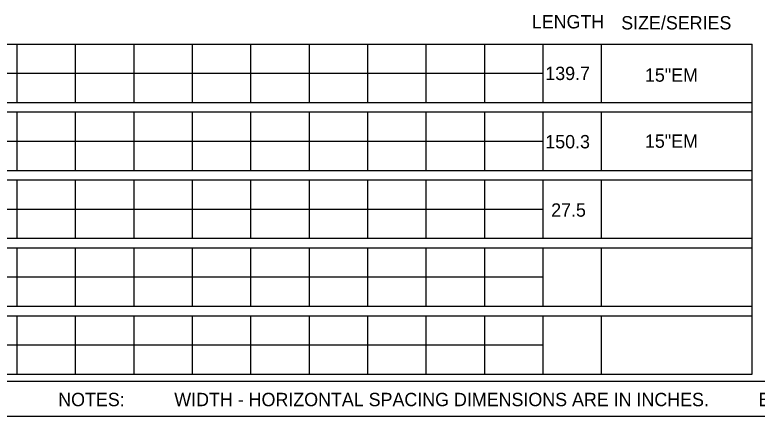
# Model space of a CAD drawing. Extents: x 10268147 to 10268469, y 2141099 to 2141204.
# Drawn here: x 10268190.55 to 10268229.47, y 2141108.6 to 2141129.63 of the extents above; entities that cross this region are included whole.
import ezdxf

# ---------------------------------------------------------------- set-up
doc = ezdxf.new("R2010")
doc.units = 0
for name, color, linetype in [('61', 7, 'Continuous'), ('GSDims', 7, 'Continuous'), ('North Arrow', 7, 'Continuous'), ('SheetLinesMisc2_dp', 7, 'Continuous'), ('TextMisc', 7, 'Continuous'), ('TextNotes', 7, 'Continuous')]:
    doc.layers.add(name, color=color, linetype=linetype)

msp = doc.modelspace()

# ---------------------------------------------------------------- linework, layer by layer
at = {"layer": '61'}
for p, q in [((10268153.875, 2141128.105), (10268229.209, 2141128.105)), ((10268190.65, 2141128.105), (10268190.65, 2141125.045)), ((10268193.714, 2141128.105), (10268193.714, 2141125.045)), ((10268196.779, 2141128.105), (10268196.779, 2141125.045)), ((10268199.843, 2141128.105), (10268199.843, 2141125.045)), ((10268202.908, 2141128.105), (10268202.908, 2141125.045)), ((10268205.972, 2141128.105), (10268205.972, 2141125.045)), ((10268209.037, 2141128.105), (10268209.037, 2141125.045)), ((10268212.102, 2141128.105), (10268212.102, 2141125.045)), ((10268215.166, 2141128.105), (10268215.166, 2141125.045)), ((10268218.232, 2141128.105), (10268218.232, 2141125.045)), ((10268221.296, 2141128.105), (10268221.296, 2141125.045)), ((10268229.209, 2141110.806), (10268229.209, 2141128.105)), ((10268153.875, 2141126.574), (10268218.232, 2141126.575)), ((10268153.875, 2141125.045), (10268229.209, 2141125.045)), ((10268153.875, 2141124.546), (10268229.209, 2141124.546)), ((10268190.65, 2141124.546), (10268190.65, 2141121.485)), ((10268193.714, 2141124.546), (10268193.714, 2141121.485)), ((10268196.779, 2141124.546), (10268196.779, 2141121.485)), ((10268199.843, 2141124.546), (10268199.843, 2141121.485)), ((10268202.908, 2141124.546), (10268202.908, 2141121.485)), ((10268205.972, 2141124.546), (10268205.972, 2141121.485)), ((10268209.037, 2141124.546), (10268209.037, 2141121.485)), ((10268212.102, 2141124.546), (10268212.102, 2141121.485)), ((10268215.166, 2141124.546), (10268215.166, 2141121.485)), ((10268218.232, 2141124.546), (10268218.232, 2141121.485)), ((10268221.296, 2141124.546), (10268221.296, 2141121.485)), ((10268153.875, 2141123.015), (10268218.232, 2141123.015)), ((10268153.875, 2141121.485), (10268229.209, 2141121.485)), ((10268153.875, 2141120.986), (10268229.209, 2141120.986)), ((10268190.65, 2141120.986), (10268190.65, 2141117.925)), ((10268193.714, 2141120.986), (10268193.714, 2141117.925)), ((10268196.779, 2141120.986), (10268196.779, 2141117.925)), ((10268199.843, 2141120.986), (10268199.843, 2141117.925)), ((10268202.908, 2141120.986), (10268202.908, 2141117.925)), ((10268205.972, 2141120.986), (10268205.972, 2141117.925)), ((10268209.037, 2141120.986), (10268209.037, 2141117.925)), ((10268212.102, 2141120.986), (10268212.102, 2141117.925)), ((10268215.166, 2141120.986), (10268215.166, 2141117.925)), ((10268218.232, 2141120.986), (10268218.232, 2141117.925)), ((10268221.296, 2141120.986), (10268221.296, 2141117.925)), ((10268153.875, 2141119.455), (10268218.232, 2141119.455)), ((10268153.875, 2141117.925), (10268229.209, 2141117.925)), ((10268153.875, 2141117.426), (10268229.209, 2141117.426)), ((10268190.65, 2141117.426), (10268190.65, 2141114.365)), ((10268193.714, 2141117.426), (10268193.714, 2141114.365)), ((10268196.779, 2141117.426), (10268196.779, 2141114.365)), ((10268199.843, 2141117.426), (10268199.843, 2141114.365)), ((10268202.908, 2141117.426), (10268202.908, 2141114.365)), ((10268205.972, 2141117.426), (10268205.972, 2141114.365)), ((10268209.037, 2141117.426), (10268209.037, 2141114.365)), ((10268212.102, 2141117.426), (10268212.102, 2141114.365)), ((10268215.166, 2141117.426), (10268215.166, 2141114.365)), ((10268218.232, 2141117.426), (10268218.232, 2141114.365)), ((10268221.296, 2141117.426), (10268221.296, 2141114.365)), ((10268153.875, 2141115.896), (10268218.232, 2141115.896)), ((10268153.875, 2141114.365), (10268229.209, 2141114.365)), ((10268153.875, 2141113.866), (10268229.209, 2141113.866)), ((10268190.65, 2141113.866), (10268190.65, 2141110.806)), ((10268193.714, 2141113.866), (10268193.714, 2141110.806)), ((10268196.779, 2141113.866), (10268196.779, 2141110.806)), ((10268199.843, 2141113.866), (10268199.843, 2141110.806)), ((10268202.908, 2141113.866), (10268202.908, 2141110.806)), ((10268205.972, 2141113.866), (10268205.972, 2141110.806)), ((10268209.037, 2141113.866), (10268209.037, 2141110.806)), ((10268212.102, 2141113.866), (10268212.102, 2141110.806)), ((10268215.166, 2141113.866), (10268215.166, 2141110.806)), ((10268218.232, 2141113.866), (10268218.232, 2141110.806)), ((10268221.296, 2141113.866), (10268221.296, 2141110.806)), ((10268153.875, 2141112.337), (10268218.232, 2141112.337)), ((10268153.875, 2141110.806), (10268229.209, 2141110.806))]:
    msp.add_line(p, q, dxfattribs=at)
at = {"layer": 'SheetLinesMisc2_dp'}
for p, q in [((10268153.14, 2141110.434), (10268306.32, 2141110.434)), ((10268153.14, 2141108.602), (10268306.32, 2141108.602))]:
    msp.add_line(p, q, dxfattribs=at)

# ---------------------------------------------------------------- texts
at = {"layer": 'GSDims'}
for p in [(10268223.587, 2141126.128), (10268223.587, 2141122.666)]:
    msp.add_text('15"EM', height=0.7, dxfattribs=at).set_placement(p)
at = {"layer": 'North Arrow'}
for s, p in [('139.7', (10268218.361, 2141126.218)), ('150.3', (10268218.361, 2141122.637)), ('27.5', (10268218.669, 2141119.055))]:
    msp.add_text(s, height=0.7, dxfattribs=at).set_placement(p)
at = {"layer": 'TextMisc'}
for s, p in [('LENGTH', (10268217.655, 2141128.924)), ('SIZE/SERIES', (10268222.343, 2141128.868))]:
    msp.add_text(s, height=0.7, dxfattribs=at).set_placement(p)
at = {"layer": 'TextNotes'}
msp.add_text('NOTES:          WIDTH - HORIZONTAL SPACING DIMENSIONS ARE IN INCHES.          END DIMENSIONS INCLUDE BORDER WIDTH, MARGIN AND BORDER RECESS.  ', height=0.7, dxfattribs=at).set_placement((10268192.823, 2141109.124))

doc.saveas('drawing.dxf')
